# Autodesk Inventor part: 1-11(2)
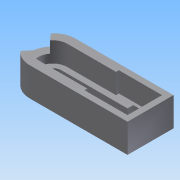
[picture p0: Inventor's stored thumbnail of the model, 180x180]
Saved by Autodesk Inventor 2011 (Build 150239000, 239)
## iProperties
Created: 2014-02
Part Number: 1-11(2)
Document SubType Name: Modeling
Designer: Administrator
Density: 1 g/cm^3
Author: Administrator
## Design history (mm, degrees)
sketch "草图1"
  geometry: L1 (-17, 8)-(17, 8); L2 (17, 8)-(17, -8); L3 (17, -8)-(-17, -8); A1 r 8 centre (-17, 0) between (-17, 8) and (-17, -8); 3 further points
  constraints: 6 end point, 2 midpoint, 2 point on circle, 1 centre point, 1 horizontal, 1 horizontal alignment, 1 parallel, 1 perpendicular, 1 vertical alignment
  dimensions: "d14" = 34 distance from line of L2 A1.centre
extrude "拉伸1" new body sketch "草图1" distance "d0" = 10; taper "d1" = 0 deg
sketch "草图2"
  geometry: L1 (0, -6)-(15, -6); L2 (15, -6)-(15, 6); L3 (15, 6)-(0, 6); L4 (0, -6)-(0, -5); L5 (0, 6)-(0, 5); L6 (0, -5)-(-17, -5); L7 (0, 5)-(-17, 5); A1 r 5 centre (-17, 0) between (-17, 5) and (-17, -5); 1 further point
  constraints: 14 end point, 2 perpendicular, 2 point on circle, 2 tangent, 1 centre point, 1 collinear
  dimensions: "d3" = 10 diameter of A1
extrude "拉伸2" cut sketch "草图2" distance "d4" = 7; taper "d5" = 0 deg
sketch "草图3"
  geometry: L1 (15, 6)-(0, 6) reference; L2 (0, -6)-(15, -6) reference; L3 (-17, -3)-(6, -3); L4 (-17, 3)-(6, 3); L5 (6, 3)-(6, 5); L6 (6, -3)-(6, -5); L7 (6, -5)-(12, -5); L8 (12, -5)-(12, 5); L9 (12, 5)-(6, 5); A1 r 5 centre (-17, 0) between (-17, 5) and (-17, -5) reference; A2 r 3 centre (-17, 0) between (-17, 3) and (-17, -3); 1 further point
  constraints: 14 end point, 5 parallel, 2 perpendicular, 2 point on circle, 2 tangent, 1 centre point, 1 coincident, 1 collinear
  dimensions: "d6" = 6 diameter of A2
extrude "拉伸3" cut sketch "草图3" distance "d8" = 7; taper "d9" = 0 deg
sketch "草图4"
  geometry: L1 (-17, -8)-(17, -8) reference; L2 (19.236, -2)-(26, -2); L3 (26, -2)-(26, 2); L4 (26, 2)-(19.236, 2); L5 (19.236, -2)-(19.236, 2); A1 r 3 centre (17, 0) between (17, -3) and (17, 3) reference; 1 further point
  constraints: 8 end point, 2 parallel, 2 perpendicular, 2 point on circle
extrude "拉伸4" cut sketch "草图4" distance "d10" = 1; taper "d11" = 0 deg
sketch "草图5"
  geometry: L1 (-24.746, 2)-(-19.236, 2) reference; L2 (-19.236, -2)-(-24.746, -2) reference; L3 (-21, 3)-(-22.96, 5.336); L4 (-22.96, -5.336)-(-21, -3); L5 (17, -8)-(-17, -8) reference; L6 (-22, 0)-(-32.999, 0); A1 r 5 centre (-17, 0) between (-17, 5) and (-17, -5) reference; A2 r 8 centre (-17, 0) between (-17, 8) and (-17, -8) reference; 1 further point
  constraints: 6 end point, 5 point on circle, 1 parallel
  dimensions: "d16" = 50 deg angle of L6 L3; "d17" = 50 deg angle of L6 L4
extrude "拉伸5" cut sketch "草图5" distance "d12" = 4; taper "d13" = 0 deg
node "实体1"
